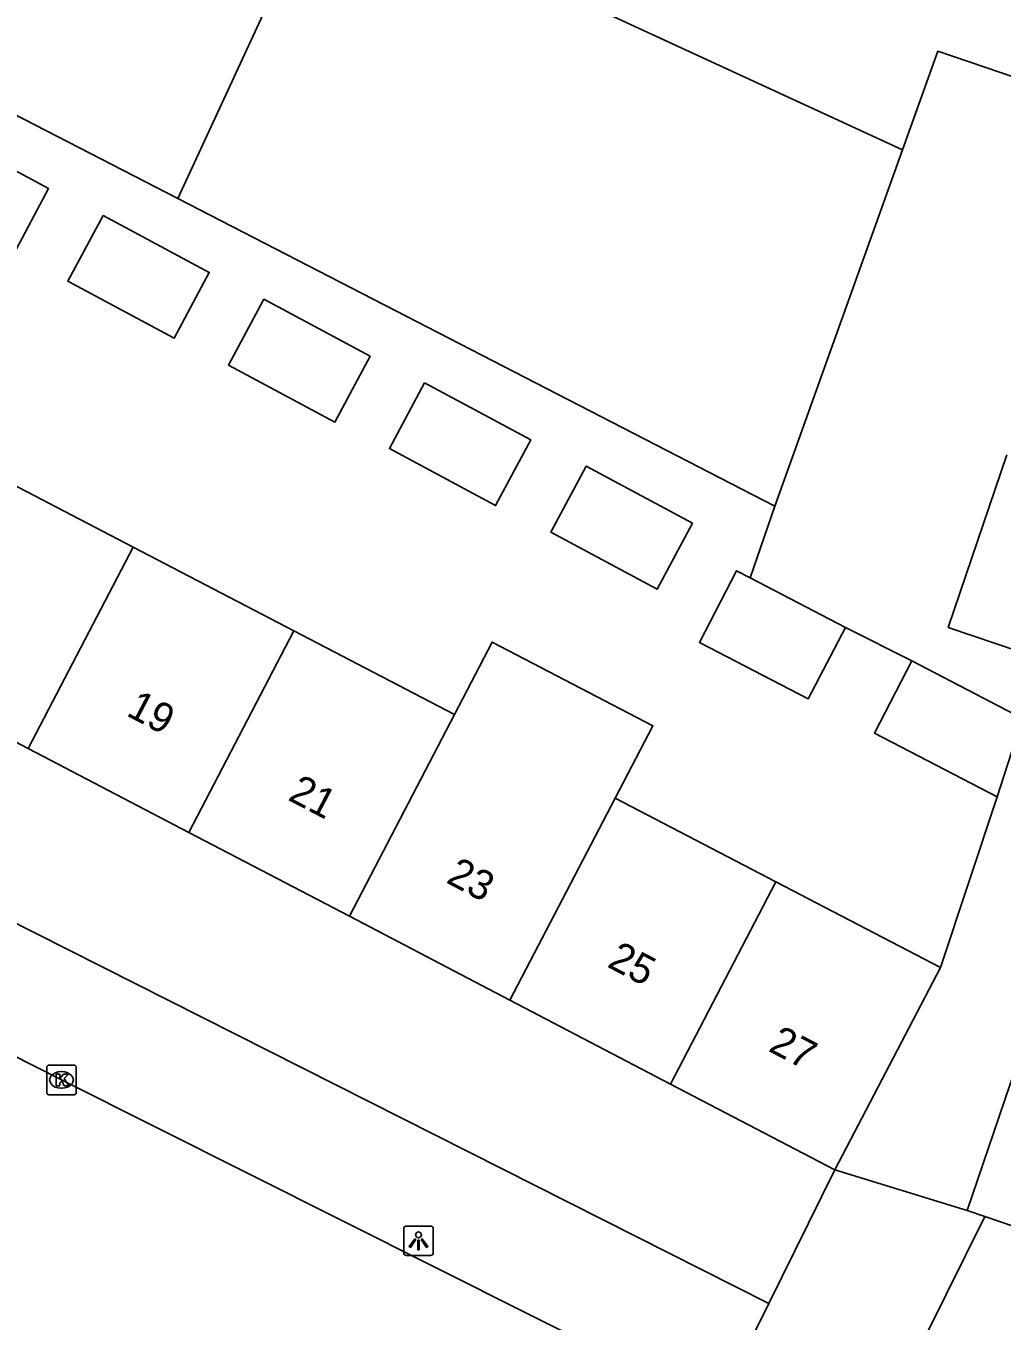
# Model space of a CAD drawing. Extents: x 162812 to 163818, y 381639 to 382470.
# Drawn here: x 163084.27 to 163117.27, y 382026.81 to 382070.61 of the extents above; entities that cross this region are included whole.
import ezdxf

# ---------------------------------------------------------------- set-up
doc = ezdxf.new("R2010")
doc.units = 0
for name, color, linetype in [('IMGEO_Kolk', 7, 'Continuous'), ('IMGEO_Lichtpunt', 7, 'Continuous'), ('IMGEO_Pand', 7, 'Continuous'), ('IMGEO_Pand_nummerreeks', 7, 'Continuous'), ('IMGEO_Rijbaan_lokaal_gesloten', 7, 'Continuous'), ('IMGEO_Rijbaan_lokaal_open', 7, 'Continuous'), ('IMGEO_Voetpad_open', 7, 'Continuous')]:
    doc.layers.add(name, color=color, linetype=linetype)

msp = doc.modelspace()

# ---------------------------------------------------------------- linework, layer by layer
at = {"layer": 'IMGEO_Kolk'}
for p, q in [((163084.97, 382034.544), (163084.97, 382035.396)), ((163085.045, 382035.47), (163085.897, 382035.47)), ((163085.458, 382035.25), (163085.483, 382035.25)), ((163085.971, 382035.396), (163085.971, 382034.544)), ((163085.481, 382034.69), (163085.456, 382034.69)), ((163085.897, 382034.47), (163085.045, 382034.47))]:
    msp.add_line(p, q, dxfattribs=at)
for points in [[(163084.97, 382034.544), (163084.97, 382035.396)], [(163085.045, 382035.47), (163085.897, 382035.47)], [(163085.291, 382035.17), (163085.414, 382035.17), (163085.414, 382035.019), (163085.544, 382035.17), (163085.708, 382035.17), (163085.562, 382035.019), (163085.715, 382034.77), (163085.563, 382034.77), (163085.478, 382034.934), (163085.414, 382034.867), (163085.414, 382034.77), (163085.291, 382034.77), (163085.291, 382035.17)], [(163085.971, 382035.396), (163085.971, 382034.544)], [(163085.897, 382034.47), (163085.045, 382034.47)]]:
    msp.add_lwpolyline(points, dxfattribs=at)
for centre, start, end in [((163085.047, 382035.394), 91.552, 178.448), ((163085.047, 382035.394), 91.552, 178.448), ((163085.895, 382035.394), 1.552, 88.448), ((163085.895, 382035.394), 1.552, 88.448), ((163085.047, 382034.546), 181.552, 268.448), ((163085.047, 382034.546), 181.552, 268.448), ((163085.895, 382034.546), 271.552, 358.448), ((163085.895, 382034.546), 271.552, 358.448)]:
    msp.add_arc(centre, 0.0765, start, end, dxfattribs=at)
for centre, major_axis, ratio, start_param, end_param in [((163085.457, 382034.97), (-0.387, 0.002), 0.722429, 4.712389, 7.853982), ((163085.482, 382034.97), (-0.39, 0.002), 0.717154, 1.570796, 4.712389)]:
    msp.add_ellipse(centre, major_axis=major_axis, ratio=ratio, start_param=start_param, end_param=end_param, dxfattribs=at)
at = {"layer": 'IMGEO_Lichtpunt'}
for p, q in [((163097.042, 382029.933), (163097.042, 382029.126)), ((163097.042, 382029.933), (163097.042, 382029.126)), ((163097.944, 382030.028), (163097.136, 382030.028)), ((163097.944, 382030.028), (163097.136, 382030.028)), ((163098.038, 382029.126), (163098.038, 382029.933)), ((163098.038, 382029.126), (163098.038, 382029.933)), ((163097.136, 382029.032), (163097.944, 382029.032)), ((163097.136, 382029.032), (163097.944, 382029.032))]:
    msp.add_line(p, q, dxfattribs=at)
for points in [[(163097.416, 382029.597), (163097.455, 382029.569), (163097.267, 382029.307), (163097.229, 382029.334), (163097.416, 382029.597)], [(163097.518, 382029.549), (163097.565, 382029.549), (163097.565, 382029.227), (163097.518, 382029.227), (163097.518, 382029.549)], [(163097.628, 382029.569), (163097.666, 382029.596), (163097.853, 382029.334), (163097.814, 382029.306), (163097.628, 382029.569)]]:
    msp.add_lwpolyline(points, dxfattribs=at)
msp.add_circle((163097.541, 382029.731), 0.0994, dxfattribs=at)
for centre, start, end in [((163097.136, 382029.933), 90, 180), ((163097.136, 382029.933), 90, 180), ((163097.944, 382029.933), 0, 90), ((163097.944, 382029.933), 0, 90), ((163097.136, 382029.126), 180, 270), ((163097.136, 382029.126), 180, 270), ((163097.944, 382029.126), 270, 0), ((163097.944, 382029.126), 270, 360)]:
    msp.add_arc(centre, 0.0946, start, end, dxfattribs=at)
at = {"layer": 'IMGEO_Pand'}
for points in [[(163089.408, 382064.775), (163064.435, 382077.65), (163065.033, 382079.863)], [(163089.408, 382064.775), (163094.344, 382075.452)], [(163094.344, 382075.452), (163113.901, 382066.416)], [(163080.25, 382064.811), (163081.443, 382067.037), (163085.037, 382065.109), (163083.843, 382062.884), (163080.25, 382064.811)], [(163109.589, 382054.37), (163113.901, 382066.416)], [(163109.589, 382054.37), (163089.408, 382064.775)], [(163086.875, 382064.205), (163090.469, 382062.277), (163089.275, 382060.052), (163085.682, 382061.979), (163086.875, 382064.205)], [(163092.316, 382061.369), (163095.909, 382059.442), (163094.715, 382057.216), (163091.122, 382059.144), (163092.316, 382061.369)], [(163097.748, 382058.542), (163101.342, 382056.614), (163100.148, 382054.389), (163096.555, 382056.317), (163097.748, 382058.542)], [(163117.434, 382056.106), (163115.449, 382050.273), (163120.246, 382048.641)], [(163087.892, 382052.981), (163082.461, 382055.81)], [(163106.806, 382053.794), (163103.212, 382055.722), (163102.019, 382053.496), (163105.612, 382051.569), (163106.806, 382053.794)], [(163084.349, 382046.178), (163087.892, 382052.981)], [(163087.892, 382052.981), (163093.324, 382050.152)], [(163108.755, 382051.947), (163108.296, 382052.186), (163107.035, 382049.765), (163110.711, 382047.851), (163111.971, 382050.272)], [(163111.971, 382050.272), (163108.755, 382051.947)], [(163093.324, 382050.152), (163089.777, 382043.341)], [(163098.755, 382047.324), (163093.324, 382050.152)], [(163104.187, 382044.495), (163105.464, 382046.948), (163100.033, 382049.778), (163098.755, 382047.324)], [(163117.107, 382044.537), (163112.953, 382046.7), (163114.222, 382049.137)], [(163117.107, 382044.537), (163117.955, 382047.193), (163114.222, 382049.137)], [(163078.921, 382049.015), (163084.349, 382046.178)], [(163098.755, 382047.324), (163095.203, 382040.505)], [(163084.349, 382046.178), (163089.777, 382043.341)], [(163100.632, 382037.667), (163104.187, 382044.495)], [(163109.618, 382041.666), (163104.187, 382044.495)], [(163089.777, 382043.341), (163095.203, 382040.505)], [(163106.058, 382034.831), (163109.618, 382041.666)], [(163115.183, 382038.768), (163109.618, 382041.666)], [(163095.203, 382040.505), (163100.632, 382037.667)], [(163111.619, 382031.924), (163115.183, 382038.768)], [(163100.632, 382037.667), (163106.058, 382034.831)], [(163118.089, 382036.41), (163116.095, 382030.549)], [(163106.058, 382034.831), (163111.619, 382031.924)], [(163132.638, 382031.462), (163130.644, 382025.6), (163116.683, 382030.349)], [(163116.095, 382030.549), (163116.683, 382030.349)]]:
    msp.add_lwpolyline(points, dxfattribs=at)
at = {"layer": 'IMGEO_Rijbaan_lokaal_gesloten'}
msp.add_lwpolyline([(163107.612, 382023.857), (163085.471, 382034.97), (163058.822, 382048.466)], dxfattribs=at)
at = {"layer": 'IMGEO_Rijbaan_lokaal_open'}
for points in [[(163113.901, 382066.416), (163115.096, 382069.756), (163121.353, 382067.628)], [(163108.755, 382051.947), (163109.589, 382054.37)], [(163114.222, 382049.137), (163111.971, 382050.272)], [(163115.183, 382038.768), (163117.107, 382044.537)], [(163116.095, 382030.549), (163111.619, 382031.924)]]:
    msp.add_lwpolyline(points, dxfattribs=at)
at = {"layer": 'IMGEO_Voetpad_open'}
for points in [[(163109.381, 382027.414), (163060.9, 382051.896), (163044.08, 382060.873), (163032.699, 382067.446)], [(163111.619, 382031.924), (163109.381, 382027.414)], [(163116.683, 382030.349), (163114.074, 382025.081), (163112.302, 382021.503)], [(163107.612, 382023.857), (163109.381, 382027.414)]]:
    msp.add_lwpolyline(points, dxfattribs=at)

# ---------------------------------------------------------------- texts
at = {"layer": 'IMGEO_Pand_nummerreeks'}
for s, rotation, p in [('19', 332.4036, (163087.625, 382047.31)), ('21', 332.4036, (163093.091, 382044.453)), ('23', 332.4064, (163098.437, 382041.658)), ('25', 332.4036, (163103.884, 382038.811)), ('27', 332.4036, (163109.331, 382035.964))]:
    msp.add_text(s, height=1, rotation=rotation, dxfattribs=at).set_placement(p)

doc.saveas('drawing.dxf')
